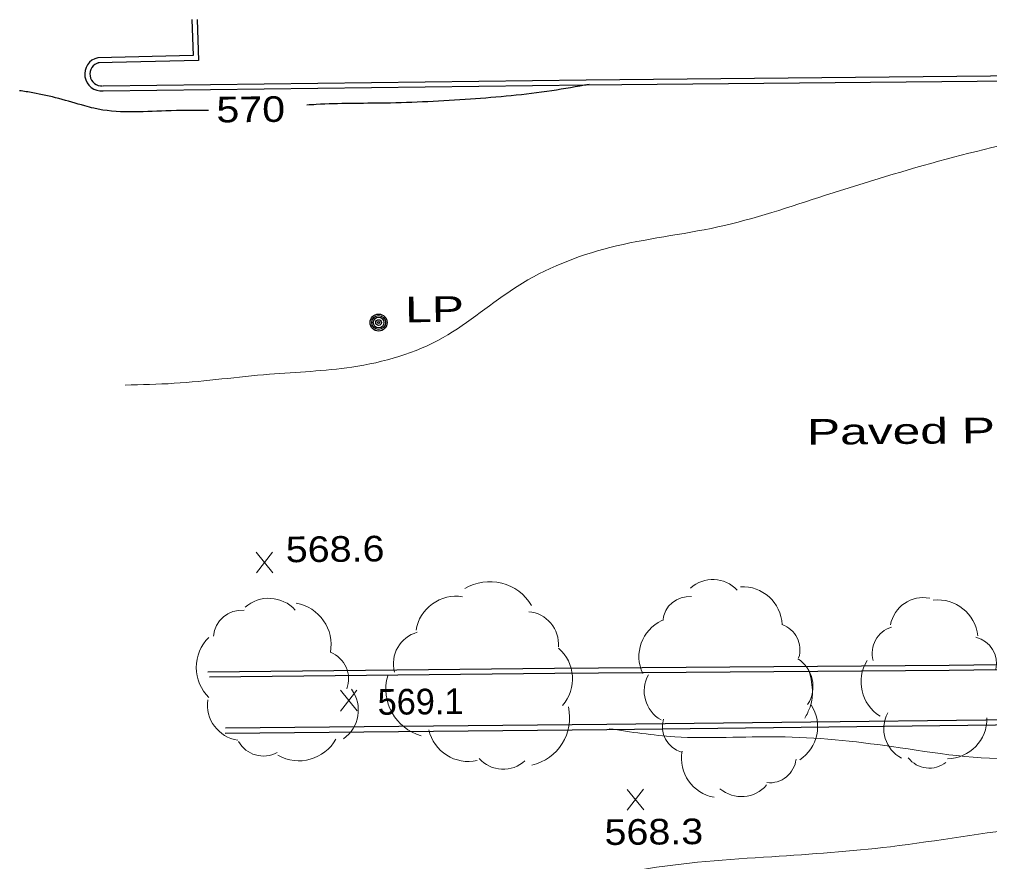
# Model space of a CAD drawing. Extents: x 2361708 to 2370558, y 6977955 to 6991887.
# Drawn here: x 2365753.8 to 2365935.4, y 6987506.7 to 6987664.4 of the extents above; entities that cross this region are included whole.
import ezdxf
from ezdxf.enums import TextEntityAlignment as Align

# ---------------------------------------------------------------- set-up
doc = ezdxf.new("R2010")
doc.units = 0
doc.header["$LTSCALE"] = 1.9
for name, color, linetype, lineweight in [('2', 7, 'Continuous', 25), ('20', 7, 'Continuous', 25), ('29', 7, 'Continuous', 13), ('31', 7, 'Continuous', 13), ('35', 7, 'Continuous', 13)]:
    doc.layers.add(name, color=color, linetype=linetype, lineweight=lineweight)

msp = doc.modelspace()

# ---------------------------------------------------------------- linework, layer by layer
at = {"layer": '2'}
for points in [[(2365786.085, 6987664.362), (2365786.309, 6987657.614), (2365768.462, 6987657.224)], [(2365787.045, 6987664.391), (2365787.298, 6987656.673), (2365768.481, 6987656.264)], [(2365769.432, 6987651.953), (2365859.836, 6987653.073), (2365979.641, 6987654.244), (2366090.366, 6987656.298)], [(2365769.441, 6987650.993), (2365859.845, 6987652.113), (2365979.65, 6987653.284), (2366090.386, 6987655.338)], [(2366083.212, 6987534.874), (2366082.769, 6987545.71), (2366020.075, 6987544.703), (2365927.793, 6987543.455), (2365853.965, 6987542.883), (2365789.048, 6987542.164)], [(2366082.252, 6987534.855), (2366081.848, 6987544.731), (2366020.095, 6987543.743), (2365927.802, 6987542.495), (2365853.974, 6987541.923), (2365789.357, 6987541.217)], [(2365792.267, 6987530.774), (2365863.754, 6987531.465), (2365972.877, 6987532.744), (2366082.591, 6987533.898), (2366123.618, 6987534.458)], [(2365792.368, 6987531.735), (2365863.744, 6987532.425), (2365972.868, 6987533.704), (2366082.252, 6987534.855)]]:
    msp.add_lwpolyline(points, dxfattribs=at)
for radius in [3.161, 2.201]:
    msp.add_arc((2365769.171, 6987654.144), radius, 102.96326, 274.90286, dxfattribs=at)
at = {"layer": '20'}
for radius in [1.6, 1.3, 1, 0.539, 0.192]:
    msp.add_circle((2365821.017, 6987607.632), radius, dxfattribs=at)
at = {"layer": '29'}
for centre, radius, start, end in [((2365883.57, 6987553.345), 6.198, 42.52058, 132.52058), ((2365841.815, 6987550.03), 9.098, 30.74805, 120.74805), ((2365889.115, 6987550.749), 7.434, 2.83304, 92.83304), ((2365800.46, 6987549.367), 6.647, 41.81521, 131.81521), ((2365835.509, 6987548.812), 7.585, 80.77994, 170.77994), ((2365879.154, 6987551.393), 4.953, 85.04443, 175.04443), ((2365922.99, 6987549.857), 6.285, 79.18469, 169.18469), ((2365925.679, 6987548.167), 7.538, 6.33668, 96.33668), ((2365795.404, 6987548.466), 5.312, 85.29448, 175.29448), ((2365804.153, 6987547.286), 7.972, 349.65386, 79.65386), ((2365848.626, 6987547.444), 6.062, 355.25064, 85.25064), ((2365877.179, 6987545.105), 7.434, 115.19214, 205.19214), ((2365894.934, 6987546.398), 4.953, 341.65833, 71.65833), ((2365918.432, 6987545.777), 5.022, 106.32334, 196.32334), ((2365794.866, 6987543.062), 7.972, 135.16176, 225.16176), ((2365829.852, 6987543.795), 6.062, 105.24456, 195.24456), ((2365931.658, 6987543.825), 5.022, 346.51186, 76.51186), ((2365849.721, 6987540.939), 7.585, 318.98842, 48.98842), ((2365810.092, 6987540.949), 5.312, 338.87642, 68.87642), ((2365896.111, 6987539.493), 6.198, 327.27183, 57.27183), ((2365918.854, 6987540.367), 7.538, 148.11432, 238.11432), ((2365831.472, 6987539.034), 9.098, 164.25522, 254.25522), ((2365876.926, 6987538.659), 6.198, 150.73188, 240.73188), ((2365810.566, 6987535.103), 6.647, 305.61863, 35.61863), ((2365795.624, 6987536.039), 6.647, 171.7578, 261.7578), ((2365847.672, 6987533.65), 9.098, 282.80115, 12.80115), ((2365895.762, 6987531.967), 7.434, 303.22191, 33.22191), ((2365921.863, 6987531.604), 6.285, 152.01082, 242.01082), ((2365879.089, 6987531.97), 4.953, 163.48907, 253.48907), ((2365927.356, 6987533.504), 7.538, 271.03523, 1.03523), ((2365837.815, 6987533.047), 7.585, 192.70678, 282.70678), ((2365799.453, 6987531.786), 5.312, 208.92386, 298.92386), ((2365806.098, 6987533.558), 7.972, 240.53919, 330.53919), ((2365885.126, 6987526.081), 7.434, 169.97194, 259.97194), ((2365844.342, 6987530.067), 6.062, 222.19493, 312.19493), ((2365894.229, 6987526.423), 4.953, 263.92938, 353.92938), ((2365924.107, 6987529.237), 5.022, 218.23995, 308.23995), ((2365888.932, 6987525.077), 6.198, 229.59787, 319.59787)]:
    msp.add_arc(centre, radius, start, end, dxfattribs=at)
at = {"layer": '31'}
for p, q in [((2365801.222, 6987560.791), (2365798.105, 6987564.642)), ((2365798.142, 6987560.762), (2365801.185, 6987564.671)), ((2365816.978, 6987534.94), (2365813.861, 6987538.79)), ((2365813.898, 6987534.91), (2365816.942, 6987538.82)), ((2365870.648, 6987516.39), (2365867.531, 6987520.24)), ((2365867.568, 6987516.361), (2365870.611, 6987520.269))]:
    msp.add_line(p, q, dxfattribs=at)
at = {"layer": '31', "lineweight": 25}
for points in [[(2365860.444, 6987652.219), (2365853.425, 6987651.022), (2365838.2, 6987649.457), (2365822.226, 6987648.715), (2365809.318, 6987648.453), (2365807.558, 6987648.336)], [(2365789.157, 6987647.34), (2365781.198, 6987647.255), (2365767.732, 6987647.746), (2365766.018, 6987648.201), (2365756.274, 6987650.658), (2365753.78, 6987651.044)]]:
    msp.add_spline(points, degree=3, dxfattribs=at)
at = {"layer": '35'}
for points in [[(2366028.105, 6987654.005), (2366015.668, 6987650.507), (2365997.479, 6987649.214), (2365974.859, 6987648.108), (2365950.199, 6987643.703), (2365927.221, 6987638.204), (2365904.694, 6987631.47), (2365884.489, 6987625.537), (2365864.295, 6987621.674), (2365846.934, 6987614.389), (2365833.074, 6987604.827), (2365816.026, 6987599.294), (2365800.568, 6987597.957), (2365782.753, 6987596.257), (2365773.556, 6987595.919)], [(2365901.612, 6987542.356), (2365902.231, 6987538.301), (2365901.766, 6987535.647), (2365900.815, 6987533.588)], [(2365864.172, 6987531.599), (2365876.457, 6987530.086), (2365895.768, 6987530.09), (2365917.097, 6987528.252), (2365941.498, 6987526.165), (2365956.785, 6987524.47), (2365960.392, 6987519.504), (2365955.908, 6987515.771), (2365942.922, 6987513.068), (2365916.805, 6987509.499), (2365894.602, 6987507.638), (2365869.984, 6987505.183), (2365855.65, 6987502.416), (2365847.032, 6987501.104)]]:
    msp.add_spline(points, degree=3, dxfattribs=at)

# ---------------------------------------------------------------- texts
at = {"layer": '2', "width": 1.45}
msp.add_text('Paved Parking', height=4.8, rotation=0.545, dxfattribs=at).set_placement((2365901.218, 6987584.744))
at = {"layer": '20', "width": 1.4}
msp.add_text('  LP', height=4.8, rotation=0.545, dxfattribs=at).set_placement((2365821.016, 6987607.632))
at = {"layer": '31', "width": 1.2}
msp.add_text(' 570 ', height=4.8, rotation=0.545, dxfattribs=at).set_placement((2365797.103, 6987645.156), align=Align.CENTER)
at = {"layer": '31', "width": 1.15}
for s, p in [('568.6', (2365803.663, 6987562.755)), ('568.3', (2365863.32, 6987509.819))]:
    msp.add_text(s, height=4.8, rotation=0.545, dxfattribs=at).set_placement(p)
at = {"layer": '31'}
msp.add_text('569.1', height=4.8, rotation=0.545, dxfattribs=at).set_placement((2365820.855, 6987534.197))

doc.saveas('drawing.dxf')
